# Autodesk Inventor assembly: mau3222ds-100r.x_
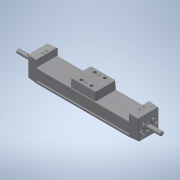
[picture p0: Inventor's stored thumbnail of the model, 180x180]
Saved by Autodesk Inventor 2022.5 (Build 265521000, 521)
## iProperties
Created: 2020-02
Part Number: mau3222ds-100r.x_
Material: 一般
Document SubType Name: Assembly
Designer: ImaoCorp
Sending System: SOLIDWORKS 2018-2018316
MC: AMD64
MC_MODEL: Intel64 Family 6 Model 60 Stepping 3, GenuineIntel
OS: Windows_NT
FRU: Parasolid Version 30.0, build 310,  6- 8-2018
FORMAT: text
GUISE: transmit
KEY: mau3222ds-100r
FILE: mau3222ds-100r.x_t
DATE: Wed Feb  5 12:00:59 2020
Author: ImaoCorp
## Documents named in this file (3)
- X:\14_SW2022-Inv2022\00_全2023-1023新製品(TCC)まで\m\mau3222ds-100r\MAU3222DS-100R.iam
- X:\14_SW2022-Inv2022\00_全2023-1023新製品(TCC)まで\m\mau3222ds-100r\mau3222ds-100r_01.ipt
- X:\14_SW2022-Inv2022\00_全2023-1023新製品(TCC)まで\m\mau3222ds-100r\mau3222ds-100r_02.ipt
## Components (2 placed, 2 different names)
1. mau3222ds-100r_01
2. mau3222ds-100r_02
